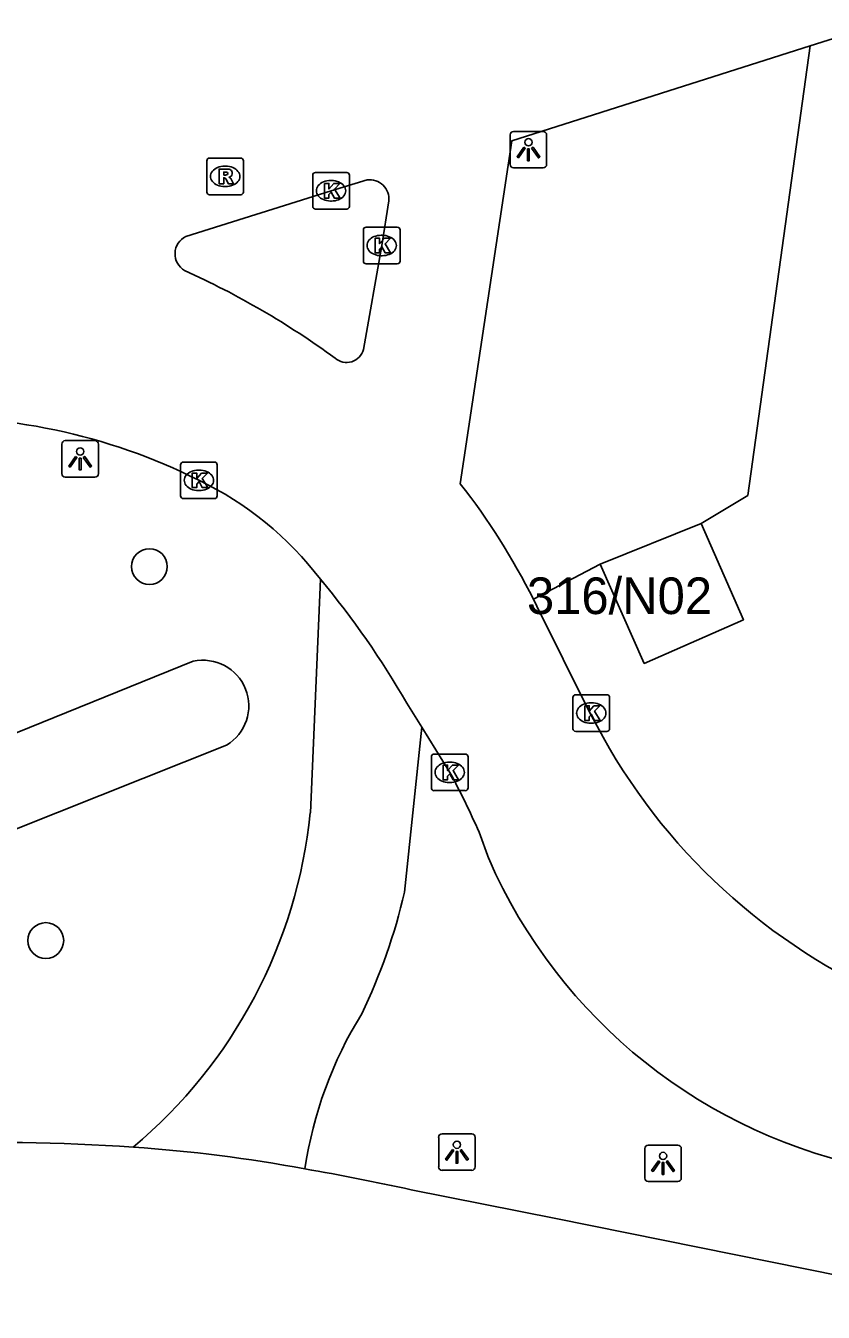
# Model space of a CAD drawing. Extents: x 161094 to 161705, y 379509 to 380907.
# Drawn here: x 161482.51 to 161504.29, y 379810.76 to 379845.9 of the extents above; entities that cross this region are included whole.
import ezdxf

# ---------------------------------------------------------------- set-up
doc = ezdxf.new("R2010")
doc.units = 0
for name, color, linetype in [('IMGEO_Boom', 7, 'Continuous'), ('IMGEO_Groenvoorziening', 7, 'Continuous'), ('IMGEO_Kolk', 7, 'Continuous'), ('IMGEO_Lichtpunt', 7, 'Continuous'), ('IMGEO_Pand', 7, 'Continuous'), ('IMGEO_Pand_nummerreeks', 7, 'Continuous'), ('IMGEO_Rijbaan_lokaal_gesloten', 7, 'Continuous'), ('IMGEO_Rioolput', 7, 'Continuous'), ('IMGEO_Voetpad_halfverhard', 7, 'Continuous'), ('IMGEO_Waterloop', 7, 'Continuous')]:
    doc.layers.add(name, color=color, linetype=linetype)

msp = doc.modelspace()

# ---------------------------------------------------------------- linework, layer by layer
at = {"layer": 'IMGEO_Boom'}
for centre in [(161485.888, 379831.123), (161483.057, 379820.91)]:
    msp.add_circle(centre, 0.489, dxfattribs=at)
at = {"layer": 'IMGEO_Groenvoorziening'}
for points in [[(161503.939, 379845.347), (161502.232, 379833.068), (161500.956, 379832.3)], [(161498.199, 379831.187), (161496.375, 379830.233)]]:
    msp.add_lwpolyline(points, dxfattribs=at)
at = {"layer": 'IMGEO_Kolk'}
for p, q in [((161490.349, 379840.962), (161490.349, 379841.814)), ((161490.424, 379841.888), (161491.276, 379841.888)), ((161491.35, 379841.814), (161491.35, 379840.962)), ((161490.837, 379841.668), (161490.862, 379841.668)), ((161490.86, 379841.108), (161490.835, 379841.108)), ((161491.276, 379840.888), (161490.424, 379840.888)), ((161491.732, 379839.468), (161491.732, 379840.32)), ((161491.807, 379840.394), (161492.659, 379840.394)), ((161492.733, 379840.32), (161492.733, 379839.468)), ((161492.22, 379840.174), (161492.245, 379840.174)), ((161492.243, 379839.614), (161492.218, 379839.614)), ((161492.659, 379839.394), (161491.807, 379839.394)), ((161486.814, 379833.98), (161487.666, 379833.98)), ((161486.739, 379833.054), (161486.739, 379833.906)), ((161487.227, 379833.76), (161487.252, 379833.76)), ((161487.74, 379833.906), (161487.74, 379833.054)), ((161487.666, 379832.98), (161486.814, 379832.98)), ((161487.25, 379833.2), (161487.225, 379833.2)), ((161497.456, 379826.697), (161497.456, 379827.549)), ((161497.531, 379827.623), (161498.383, 379827.623)), ((161497.944, 379827.403), (161497.969, 379827.403)), ((161498.457, 379827.549), (161498.457, 379826.697)), ((161498.383, 379826.623), (161497.531, 379826.623)), ((161497.967, 379826.843), (161497.942, 379826.843)), ((161493.59, 379825.078), (161493.59, 379825.93)), ((161493.665, 379826.004), (161494.517, 379826.004)), ((161494.591, 379825.93), (161494.591, 379825.078)), ((161494.078, 379825.784), (161494.103, 379825.784)), ((161494.101, 379825.224), (161494.076, 379825.224)), ((161494.517, 379825.004), (161493.665, 379825.004))]:
    msp.add_line(p, q, dxfattribs=at)
for points in [[(161490.349, 379840.962), (161490.349, 379841.814)], [(161490.424, 379841.888), (161491.276, 379841.888)], [(161491.35, 379841.814), (161491.35, 379840.962)], [(161490.67, 379841.588), (161490.793, 379841.588), (161490.793, 379841.437), (161490.923, 379841.588), (161491.087, 379841.588), (161490.941, 379841.437), (161491.094, 379841.188), (161490.942, 379841.188), (161490.857, 379841.352), (161490.793, 379841.285), (161490.793, 379841.188), (161490.67, 379841.188), (161490.67, 379841.588)], [(161491.276, 379840.888), (161490.424, 379840.888)], [(161491.732, 379839.468), (161491.732, 379840.32)], [(161491.807, 379840.394), (161492.659, 379840.394)], [(161492.733, 379840.32), (161492.733, 379839.468)], [(161492.053, 379840.094), (161492.176, 379840.094), (161492.176, 379839.943), (161492.306, 379840.094), (161492.47, 379840.094), (161492.324, 379839.943), (161492.477, 379839.694), (161492.325, 379839.694), (161492.24, 379839.858), (161492.176, 379839.791), (161492.176, 379839.694), (161492.053, 379839.694), (161492.053, 379840.094)], [(161492.659, 379839.394), (161491.807, 379839.394)], [(161486.814, 379833.98), (161487.666, 379833.98)], [(161486.739, 379833.054), (161486.739, 379833.906)], [(161487.06, 379833.68), (161487.183, 379833.68), (161487.183, 379833.529), (161487.313, 379833.68), (161487.477, 379833.68), (161487.331, 379833.529), (161487.484, 379833.28), (161487.332, 379833.28), (161487.247, 379833.444), (161487.183, 379833.377), (161487.183, 379833.28), (161487.06, 379833.28), (161487.06, 379833.68)], [(161487.74, 379833.906), (161487.74, 379833.054)], [(161487.666, 379832.98), (161486.814, 379832.98)], [(161497.456, 379826.697), (161497.456, 379827.549)], [(161497.531, 379827.623), (161498.383, 379827.623)], [(161497.777, 379827.323), (161497.9, 379827.323), (161497.9, 379827.172), (161498.03, 379827.323), (161498.194, 379827.323), (161498.048, 379827.172), (161498.201, 379826.923), (161498.049, 379826.923), (161497.964, 379827.087), (161497.9, 379827.02), (161497.9, 379826.923), (161497.777, 379826.923), (161497.777, 379827.323)], [(161498.457, 379827.549), (161498.457, 379826.697)], [(161498.383, 379826.623), (161497.531, 379826.623)], [(161493.59, 379825.078), (161493.59, 379825.93)], [(161493.665, 379826.004), (161494.517, 379826.004)], [(161494.591, 379825.93), (161494.591, 379825.078)], [(161493.911, 379825.704), (161494.034, 379825.704), (161494.034, 379825.553), (161494.164, 379825.704), (161494.328, 379825.704), (161494.182, 379825.553), (161494.335, 379825.304), (161494.183, 379825.304), (161494.098, 379825.468), (161494.034, 379825.401), (161494.034, 379825.304), (161493.911, 379825.304), (161493.911, 379825.704)], [(161494.517, 379825.004), (161493.665, 379825.004)]]:
    msp.add_lwpolyline(points, dxfattribs=at)
for centre, start, end in [((161490.426, 379841.812), 91.552, 178.448), ((161490.426, 379841.812), 91.552, 178.448), ((161491.274, 379841.812), 1.552, 88.448), ((161491.274, 379841.812), 1.552, 88.448), ((161490.426, 379840.964), 181.552, 268.448), ((161490.426, 379840.964), 181.552, 268.448), ((161491.274, 379840.964), 271.552, 358.448), ((161491.274, 379840.964), 271.552, 358.448), ((161491.809, 379840.318), 91.552, 178.448), ((161491.809, 379840.318), 91.552, 178.448), ((161492.657, 379840.318), 1.552, 88.448), ((161492.657, 379840.318), 1.552, 88.448), ((161491.809, 379839.47), 181.552, 268.448), ((161491.809, 379839.47), 181.552, 268.448), ((161492.657, 379839.47), 271.552, 358.448), ((161492.657, 379839.47), 271.552, 358.448), ((161486.816, 379833.904), 91.552, 178.448), ((161486.816, 379833.904), 91.552, 178.448), ((161487.664, 379833.904), 1.552, 88.448), ((161487.664, 379833.904), 1.552, 88.448), ((161486.816, 379833.056), 181.552, 268.448), ((161486.816, 379833.056), 181.552, 268.448), ((161487.664, 379833.056), 271.552, 358.448), ((161487.664, 379833.056), 271.552, 358.448), ((161497.533, 379827.547), 91.552, 178.448), ((161497.533, 379827.547), 91.552, 178.448), ((161498.381, 379827.547), 1.552, 88.448), ((161498.381, 379827.547), 1.552, 88.448), ((161497.533, 379826.699), 181.552, 268.448), ((161497.533, 379826.699), 181.552, 268.448), ((161498.381, 379826.699), 271.552, 358.448), ((161498.381, 379826.699), 271.552, 358.448), ((161493.667, 379825.928), 91.552, 178.448), ((161493.667, 379825.928), 91.552, 178.448), ((161494.515, 379825.928), 1.552, 88.448), ((161494.515, 379825.928), 1.552, 88.448), ((161493.667, 379825.08), 181.552, 268.448), ((161493.667, 379825.08), 181.552, 268.448), ((161494.515, 379825.08), 271.552, 358.448), ((161494.515, 379825.08), 271.552, 358.448)]:
    msp.add_arc(centre, 0.0765, start, end, dxfattribs=at)
for centre, major_axis, ratio, start_param, end_param in [((161490.836, 379841.388), (-0.387, 0.002), 0.722429, 4.712389, 7.853982), ((161490.861, 379841.388), (-0.39, 0.002), 0.717154, 1.570796, 4.712389), ((161492.219, 379839.894), (-0.387, 0.002), 0.722429, 4.712389, 7.853982), ((161492.244, 379839.894), (-0.39, 0.002), 0.717154, 1.570796, 4.712389), ((161487.226, 379833.48), (-0.387, 0.002), 0.722429, 4.712389, 7.853982), ((161487.251, 379833.48), (-0.39, 0.002), 0.717154, 1.570796, 4.712389), ((161497.943, 379827.123), (-0.387, 0.002), 0.722429, 4.712389, 7.853982), ((161497.968, 379827.123), (-0.39, 0.002), 0.717154, 1.570796, 4.712389), ((161494.077, 379825.504), (-0.387, 0.002), 0.722429, 4.712389, 7.853982), ((161494.102, 379825.504), (-0.39, 0.002), 0.717154, 1.570796, 4.712389)]:
    msp.add_ellipse(centre, major_axis=major_axis, ratio=ratio, start_param=start_param, end_param=end_param, dxfattribs=at)
at = {"layer": 'IMGEO_Lichtpunt'}
for p, q in [((161495.742, 379842.915), (161495.742, 379842.108)), ((161495.742, 379842.915), (161495.742, 379842.108)), ((161496.644, 379843.01), (161495.836, 379843.01)), ((161496.644, 379843.01), (161495.836, 379843.01)), ((161496.738, 379842.108), (161496.738, 379842.915)), ((161496.738, 379842.108), (161496.738, 379842.915)), ((161495.836, 379842.014), (161496.644, 379842.014)), ((161495.836, 379842.014), (161496.644, 379842.014)), ((161483.497, 379834.469), (161483.497, 379833.662)), ((161483.497, 379834.469), (161483.497, 379833.662)), ((161484.399, 379834.564), (161483.591, 379834.564)), ((161484.399, 379834.564), (161483.591, 379834.564)), ((161484.493, 379833.662), (161484.493, 379834.469)), ((161484.493, 379833.662), (161484.493, 379834.469)), ((161483.591, 379833.568), (161484.399, 379833.568)), ((161483.591, 379833.568), (161484.399, 379833.568)), ((161493.789, 379815.535), (161493.789, 379814.728)), ((161493.789, 379815.535), (161493.789, 379814.728)), ((161494.691, 379815.63), (161493.883, 379815.63)), ((161494.691, 379815.63), (161493.883, 379815.63)), ((161494.785, 379814.728), (161494.785, 379815.535)), ((161494.785, 379814.728), (161494.785, 379815.535)), ((161499.419, 379815.228), (161499.419, 379814.421)), ((161499.419, 379815.228), (161499.419, 379814.421)), ((161500.321, 379815.323), (161499.513, 379815.323)), ((161500.321, 379815.323), (161499.513, 379815.323)), ((161500.415, 379814.421), (161500.415, 379815.228)), ((161500.415, 379814.421), (161500.415, 379815.228)), ((161493.883, 379814.634), (161494.691, 379814.634)), ((161493.883, 379814.634), (161494.691, 379814.634)), ((161499.513, 379814.327), (161500.321, 379814.327)), ((161499.513, 379814.327), (161500.321, 379814.327))]:
    msp.add_line(p, q, dxfattribs=at)
for points in [[(161496.116, 379842.579), (161496.155, 379842.551), (161495.967, 379842.289), (161495.929, 379842.316), (161496.116, 379842.579)], [(161496.218, 379842.531), (161496.265, 379842.531), (161496.265, 379842.209), (161496.218, 379842.209), (161496.218, 379842.531)], [(161496.328, 379842.551), (161496.366, 379842.578), (161496.553, 379842.316), (161496.514, 379842.288), (161496.328, 379842.551)], [(161483.871, 379834.133), (161483.91, 379834.105), (161483.722, 379833.843), (161483.684, 379833.87), (161483.871, 379834.133)], [(161483.973, 379834.085), (161484.02, 379834.085), (161484.02, 379833.763), (161483.973, 379833.763), (161483.973, 379834.085)], [(161484.083, 379834.105), (161484.121, 379834.132), (161484.308, 379833.87), (161484.269, 379833.842), (161484.083, 379834.105)], [(161494.163, 379815.199), (161494.202, 379815.171), (161494.014, 379814.909), (161493.976, 379814.936), (161494.163, 379815.199)], [(161494.265, 379815.151), (161494.312, 379815.151), (161494.312, 379814.829), (161494.265, 379814.829), (161494.265, 379815.151)], [(161494.375, 379815.171), (161494.413, 379815.198), (161494.6, 379814.936), (161494.561, 379814.908), (161494.375, 379815.171)], [(161499.793, 379814.892), (161499.832, 379814.864), (161499.644, 379814.602), (161499.606, 379814.629), (161499.793, 379814.892)], [(161499.895, 379814.844), (161499.942, 379814.844), (161499.942, 379814.522), (161499.895, 379814.522), (161499.895, 379814.844)], [(161500.005, 379814.864), (161500.043, 379814.891), (161500.23, 379814.629), (161500.191, 379814.601), (161500.005, 379814.864)]]:
    msp.add_lwpolyline(points, dxfattribs=at)
for centre in [(161496.241, 379842.713), (161483.996, 379834.267), (161494.288, 379815.333), (161499.918, 379815.026)]:
    msp.add_circle(centre, 0.0994, dxfattribs=at)
for centre, start, end in [((161495.836, 379842.915), 90, 180), ((161495.836, 379842.915), 90, 180), ((161496.644, 379842.915), 0, 90), ((161496.644, 379842.915), 0, 90), ((161495.836, 379842.108), 180, 270), ((161495.836, 379842.108), 180, 270), ((161496.644, 379842.108), 270, 0), ((161496.644, 379842.108), 270, 360), ((161483.591, 379834.469), 90, 180), ((161483.591, 379834.469), 90, 180), ((161484.399, 379834.469), 0, 90), ((161484.399, 379834.469), 0, 90), ((161483.591, 379833.662), 180, 270), ((161483.591, 379833.662), 180, 270), ((161484.399, 379833.662), 270, 0), ((161484.399, 379833.662), 270, 360), ((161493.883, 379815.535), 90, 180), ((161493.883, 379815.535), 90, 180), ((161494.691, 379815.535), 0, 90), ((161494.691, 379815.535), 0, 90), ((161499.513, 379815.228), 90, 180), ((161499.513, 379815.228), 90, 180), ((161500.321, 379815.228), 0, 90), ((161500.321, 379815.228), 0, 90), ((161493.883, 379814.728), 180, 270), ((161493.883, 379814.728), 180, 270), ((161494.691, 379814.728), 270, 0), ((161494.691, 379814.728), 270, 360), ((161499.513, 379814.421), 180, 270), ((161499.513, 379814.421), 180, 270), ((161500.321, 379814.421), 270, 0), ((161500.321, 379814.421), 270, 360)]:
    msp.add_arc(centre, 0.0946, start, end, dxfattribs=at)
at = {"layer": 'IMGEO_Pand'}
for points in [[(161500.956, 379832.3), (161498.199, 379831.187)], [(161500.956, 379832.3), (161502.113, 379829.674), (161499.404, 379828.481), (161498.199, 379831.187)]]:
    msp.add_lwpolyline(points, dxfattribs=at)
at = {"layer": 'IMGEO_Rijbaan_lokaal_gesloten'}
for points in [[(161503.939, 379845.347), (161514.99, 379848.832)], [(161494.38, 379833.386), (161495.787, 379842.75), (161503.939, 379845.347)], [(161486.884, 379840.14), (161490.85, 379841.388), (161491.835, 379841.685)], [(161492.426, 379841.113), (161492.233, 379839.894)], [(161492.233, 379839.894), (161491.736, 379837.053)], [(161498.28, 379826.466), (161497.906, 379827.145), (161496.47, 379830.041), (161496.375, 379830.233)], [(161492.921, 379827.39), (161493.327, 379826.735)], [(161493.327, 379826.735), (161494.091, 379825.504)], [(161494.891, 379823.867), (161495.157, 379823.146)], [(161509.666, 379810.757), (161496.987, 379813.314), (161493.035, 379814.104)]]:
    msp.add_lwpolyline(points, dxfattribs=at)
for centre, radius, start, end in [((161491.907, 379841.168), 0.522, 353.9493, 97.9226), ((161487.114, 379839.666), 0.527, 115.8637, 239.8257), ((161477.292, 379818.055), 23.214, 53.9329, 65.6895), ((161491.275, 379837.178), 0.478, 228.6946, 344.8256), ((161480.014, 379819.128), 16.069, 63.2743, 93.106), ((161483.32, 379825.278), 9.091, 37.2239, 64.4573), ((161479.54, 379821.788), 18.834, 26.6382, 38.0073), ((161472.344, 379815.557), 23.736, 29.9009, 39.8808), ((161512.831, 379834.579), 16.66, 209.1437, 248.1335), ((161478.103, 379816.677), 18.263, 23.1854, 28.904), ((161508.497, 379828.972), 14.557, 203.5903, 259.3176), ((161481.636, 379760.171), 55.226, 86.0407, 92.3337), ((161482.82, 379775.556), 39.796, 79.409, 86.2116), ((161478.722, 379748.924), 66.733, 77.61461, 80.1532)]:
    msp.add_arc(centre, radius, start, end, dxfattribs=at)
at = {"layer": 'IMGEO_Rioolput'}
for p, q in [((161487.456, 379841.355), (161487.456, 379842.207)), ((161487.531, 379842.281), (161488.383, 379842.281)), ((161487.944, 379842.061), (161487.969, 379842.061)), ((161488.457, 379842.207), (161488.457, 379841.355)), ((161487.967, 379841.501), (161487.942, 379841.501)), ((161488.383, 379841.281), (161487.531, 379841.281))]:
    msp.add_line(p, q, dxfattribs=at)
for points in [[(161487.456, 379841.355), (161487.456, 379842.207)], [(161487.531, 379842.281), (161488.383, 379842.281)], [(161488.457, 379842.207), (161488.457, 379841.355)], [(161488.045, 379841.979), (161487.793, 379841.981), (161487.793, 379841.581)], [(161487.793, 379841.581), (161487.917, 379841.581), (161487.917, 379841.743), (161487.928, 379841.743)], [(161487.971, 379841.9), (161487.917, 379841.9), (161487.917, 379841.819)], [(161487.917, 379841.819), (161487.969, 379841.819)], [(161487.975, 379841.714), (161488.046, 379841.581), (161488.186, 379841.581), (161488.121, 379841.707)], [(161488.383, 379841.281), (161487.531, 379841.281)]]:
    msp.add_lwpolyline(points, dxfattribs=at)
for centre, radius, start, end in [((161487.533, 379842.205), 0.0765, 91.552, 178.448), ((161487.533, 379842.205), 0.0765, 91.552, 178.448), ((161488.381, 379842.205), 0.0765, 1.552, 88.448), ((161488.381, 379842.205), 0.0765, 1.552, 88.448), ((161487.927, 379841.69), 0.0533, 26.0293, 88.6989), ((161487.953, 379842.008), 0.19, 274.7715, 282.9687), ((161487.977, 379841.804), 0.0964, 77.0061, 93.1865), ((161487.991, 379841.861), 0.0378, 276.6634, 79.6772), ((161488.044, 379841.869), 0.109, 350.3612, 89.416), ((161488.042, 379841.869), 0.112, 277.5842, 350.9817), ((161488.026, 379841.654), 0.108, 29.5134, 73.7905), ((161487.533, 379841.357), 0.0765, 181.552, 268.448), ((161487.533, 379841.357), 0.0765, 181.552, 268.448), ((161488.381, 379841.357), 0.0765, 271.552, 358.448), ((161488.381, 379841.357), 0.0765, 271.552, 358.448)]:
    msp.add_arc(centre, radius, start, end, dxfattribs=at)
for centre, major_axis, ratio, start_param, end_param in [((161487.943, 379841.781), (-0.387, 0.002), 0.722429, 4.712389, 7.853982), ((161487.968, 379841.781), (-0.39, 0.002), 0.717154, 1.570796, 4.712389)]:
    msp.add_ellipse(centre, major_axis=major_axis, ratio=ratio, start_param=start_param, end_param=end_param, dxfattribs=at)
at = {"layer": 'IMGEO_Voetpad_halfverhard'}
for points in [[(161490.284, 379824.397), (161490.559, 379830.777)], [(161492.855, 379822.23), (161493.327, 379826.735)]]:
    msp.add_lwpolyline(points, dxfattribs=at)
for centre, radius, start, end in [((161476.574, 379825.81), 13.782, 310.0851, 354.1164), ((161477.388, 379825.804), 15.875, 334.257, 346.9893), ((161501.281, 379812.989), 11.274, 148.3214, 171.402)]:
    msp.add_arc(centre, radius, start, end, dxfattribs=at)
at = {"layer": 'IMGEO_Waterloop'}
msp.add_lwpolyline([(161487.997, 379826.248), (161463.782, 379816.609), (161462.95, 379818.759), (161487.084, 379828.537)], dxfattribs=at)
msp.add_arc((161487.354, 379827.318), 1.248, 301.0173, 102.4732, dxfattribs=at)

# ---------------------------------------------------------------- texts
at = {"layer": 'IMGEO_Pand_nummerreeks'}
msp.add_text('316/N02', height=1, dxfattribs=at).set_placement((161496.2, 379829.827))

doc.saveas('drawing.dxf')
